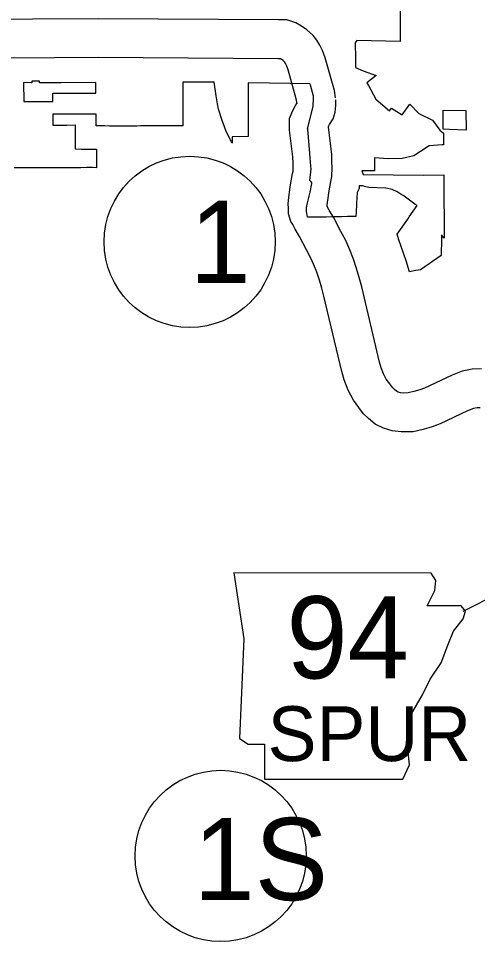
# Model space of a CAD drawing. Extents: x 670147 to 673275, y 705573 to 707613.
# Drawn here: x 670649.9 to 670703, y 707193.3 to 707300.1 of the extents above; entities that cross this region are included whole.
import ezdxf

# ---------------------------------------------------------------- set-up
doc = ezdxf.new("R2010")
doc.units = 0
for name, color, linetype in [('10', 7, 'Continuous'), ('21', 7, 'Continuous'), ('27', 7, 'Continuous'), ('6', 7, 'Continuous')]:
    doc.layers.add(name, color=color, linetype=linetype)

msp = doc.modelspace()

# ---------------------------------------------------------------- linework, layer by layer
at = {"layer": '10'}
for points in [[(670686.58, 707290.93), (670686.45, 707291.76), (670685.39, 707295.54), (670685.09, 707296.38), (670684.78, 707297), (670684.42, 707297.58), (670684.01, 707298.13), (670683.27, 707298.79), (670682.63, 707299.22), (670682, 707299.6), (670680.95, 707299.92), (670679.98, 707299.93), (670659.13, 707300.07), (670643.9, 707299.97), (670623.24, 707299.95), (670622.57, 707299.9), (670622.06, 707299.8), (670621.6, 707299.73), (670620.82, 707299.58), (670620.26, 707299.49), (670616.24, 707299.62)], [(670682.13, 707290.24), (670682.04, 707290.81), (670681.11, 707294.17), (670680.95, 707294.59), (670680.84, 707294.8), (670680.69, 707295.06), (670680.67, 707295.08), (670680.51, 707295.22), (670680.22, 707295.42), (670680.2, 707295.43), (670679.93, 707295.43), (670659.13, 707295.57), (670643.92, 707295.47), (670623.4, 707295.45), (670623.15, 707295.43), (670622.85, 707295.37), (670622.38, 707295.29), (670621.61, 707295.15), (670620.58, 707294.97), (670602.62, 707295.57)], [(670703.3, 707255.07), (670702.94, 707255.06), (670702.53, 707254.98), (670701.84, 707254.71), (670698.67, 707253.21), (670697.75, 707252.85), (670696.71, 707252.57), (670695.54, 707252.3), (670694.16, 707252.27), (670693.12, 707252.4), (670692.14, 707252.7), (670691.17, 707253.19), (670690.4, 707253.82), (670689.83, 707254.38), (670689.28, 707255.11), (670688.64, 707255.96), (670688.03, 707257.1), (670687.56, 707258.29), (670687.3, 707259.27), (670685.24, 707267.97), (670685, 707268.91), (670684.71, 707269.81), (670684.42, 707270.74), (670684.06, 707271.6), (670683.7, 707272.46), (670683.21, 707273.35), (670682.43, 707274.86), (670681.91, 707275.74), (670681.64, 707276.27), (670681.43, 707276.63), (670681.13, 707277.5), (670681.13, 707278.15), (670681.11, 707278.64), (670681.17, 707279.37), (670681.26, 707279.96), (670681.35, 707280.62), (670681.62, 707282.15), (670681.69, 707282.43), (670681.7, 707282.8), (670681.67, 707283.37), (670681.66, 707284.08), (670681.26, 707287.18), (670681.24, 707287.75), (670681.27, 707288.54), (670681.52, 707289.17), (670681.79, 707289.77), (670682.12, 707290.28), (670682.11, 707290.5)], [(670703.47, 707259.58), (670702.39, 707259.55), (670701.24, 707259.3), (670700.08, 707258.86), (670696.88, 707257.34), (670696.34, 707257.13), (670695.62, 707256.94), (670694.96, 707256.79), (670694.39, 707256.77), (670694.08, 707256.81), (670693.83, 707256.89), (670693.63, 707256.99), (670693.41, 707257.17), (670693.22, 707257.36), (670692.87, 707257.82), (670692.45, 707258.38), (670692.12, 707259), (670691.84, 707259.7), (670691.66, 707260.36), (670689.61, 707269.05), (670689.33, 707270.15), (670689, 707271.17), (670688.65, 707272.27), (670688.22, 707273.33), (670687.76, 707274.41), (670687.19, 707275.47), (670686.37, 707277.04), (670685.85, 707277.92), (670685.63, 707278.36), (670685.62, 707278.55), (670685.64, 707278.82), (670685.72, 707279.31), (670685.8, 707279.94), (670686.03, 707281.24), (670686.17, 707281.83), (670686.2, 707282.84), (670686.17, 707283.5), (670686.16, 707284.38), (670685.75, 707287.58), (670685.75, 707287.61), (670685.75, 707287.61), (670685.9, 707287.84), (670686.32, 707288.47), (670686.53, 707289.25), (670686.63, 707290.04), (670686.6, 707290.67)]]:
    msp.add_lwpolyline(points, dxfattribs=at)
at = {"layer": '21'}
msp.add_line((670701.34, 707231.53), (670721.03, 707241.6), dxfattribs=at)
msp.add_lwpolyline([(670674.83, 707235.97), (670675.97, 707228.36), (670675.46, 707216.81), (670676.48, 707216.18), (670678.38, 707216.18), (670678.38, 707212.12), (670694.37, 707212.12), (670695.13, 707213.77), (670694.88, 707216.43), (670695.26, 707219.48), (670696.65, 707221.89), (670697.54, 707223.67), (670698.81, 707225.57), (670699.57, 707227.6), (670700.21, 707229.25), (670701.35, 707230.65), (670701.6, 707231.53), (670701.09, 707232.17), (670697.16, 707232.17), (670698.05, 707233.94), (670698.17, 707235.09), (670697.65, 707235.96)], close=True, dxfattribs=at)
at = {"layer": '27'}
for centre in [(670669.72, 707274.26), (670673.3, 707203.24)]:
    msp.add_circle(centre, 9.9, dxfattribs=at)
at = {"layer": '6'}
for points in [[(670694.08, 707307.34), (670694.06, 707297.42), (670689.06, 707297.54), (670689.03, 707297.54), (670688.85, 707297.28), (670688.87, 707295.5), (670688.87, 707294.6), (670688.87, 707294.41), (670689.78, 707294.03), (670691.27, 707293.48), (670690.2, 707292.65), (670690.41, 707292.33), (670691.24, 707290.77), (670692.82, 707289.42), (670693.04, 707289.73), (670694.27, 707288.96), (670695.18, 707290.19), (670696.23, 707289.11), (670697.81, 707288.32), (670698.62, 707287.19), (670699.05, 707286.83), (670699.06, 707285.86), (670699.06, 707285.49), (670699.03, 707285.49), (670698.89, 707285.47), (670697.41, 707285.37), (670696.39, 707284.7), (670695.64, 707284.21), (670694.3, 707283.91), (670692.68, 707283.87), (670691.1, 707283.96), (670691.1, 707283.58), (670691.1, 707282.46), (670689.63, 707282.49), (670689.77, 707282.03), (670696.72, 707281.99), (670699.09, 707282.02), (670699.11, 707279.03), (670699.13, 707277.17), (670699.13, 707276.92), (670699.15, 707274.69), (670698.82, 707275.08), (670698.82, 707274.78), (670698.82, 707274.59), (670698.81, 707272.7), (670696.39, 707271.02), (670695.86, 707270.93), (670695.15, 707270.81), (670694.75, 707272.05), (670694.44, 707272.96), (670693.91, 707274.51), (670693.69, 707275.13), (670694.92, 707276.9), (670695.11, 707277.17), (670696, 707278.45), (670695.76, 707278.63), (670694.53, 707279.54), (670694.4, 707279.63), (670694.17, 707279.75), (670693.7, 707280.06), (670693.13, 707280.31), (670692.39, 707280.46), (670690.44, 707280.55), (670689.91, 707280.67), (670689.73, 707280.72), (670689.32, 707280.72), (670689.32, 707280.44), (670689.09, 707279.95), (670689.02, 707278.72), (670688.96, 707277.56), (670688.94, 707277.27), (670688.94, 707277.19), (670688.81, 707277.19), (670687.98, 707277.18), (670687.26, 707277.17), (670687.15, 707277.16), (670686.91, 707277.16), (670686.33, 707277.15), (670685.5, 707277.13), (670683.53, 707277.11), (670683.34, 707277.11), (670683.29, 707277.35), (670683.25, 707277.56), (670683.23, 707277.77), (670683.23, 707277.98), (670683.24, 707278.19), (670683.24, 707278.22), (670683.24, 707278.26), (670683.26, 707278.4), (670683.29, 707278.61), (670683.64, 707279.99), (670683.85, 707281.02), (670683.81, 707281.14), (670683.83, 707281.14), (670683.62, 707281.34), (670683.75, 707282.71), (670683.74, 707283), (670683.6, 707284.48)], [(670683.6, 707284.48), (670683.36, 707287.31), (670683.4, 707287.34), (670683.35, 707287.34), (670683.75, 707288.97), (670683.98, 707289.97), (670684.02, 707290.84), (670684.03, 707291.1), (670683.68, 707292.39), (670683.65, 707292.52), (670678.96, 707292.61), (670676.48, 707292.65), (670676.48, 707291.34), (670676.49, 707288.45), (670676.49, 707287.55), (670676.49, 707286.45), (670674.64, 707286.4), (670674.63, 707285.67), (670673.94, 707287.02), (670673.76, 707287.58), (670673.49, 707288.3), (670673.06, 707289.62), (670672.92, 707290.22), (670672.78, 707291.16), (670672.55, 707292.73), (670668.91, 707292.72), (670668.91, 707292.09), (670668.92, 707291.42), (670668.93, 707290.76), (670668.93, 707290.23), (670668.93, 707289.71), (670668.94, 707289.18), (670668.94, 707288.55), (670668.94, 707287.69), (670668.47, 707287.69), (670667.29, 707287.68), (670667.03, 707287.68), (670666.76, 707287.67), (670666.24, 707287.67), (670665.71, 707287.67), (670665.32, 707287.66), (670665.18, 707287.67), (670664.66, 707287.67), (670664.13, 707287.66), (670664.02, 707287.66), (670663.6, 707287.65), (670663.08, 707287.65), (670662.55, 707287.65), (670662.45, 707287.65), (670662.38, 707287.65), (670662.02, 707287.65), (670661.5, 707287.65), (670660.97, 707287.65), (670660.45, 707287.65), (670659.92, 707287.66), (670659.08, 707287.66), (670658.91, 707287.66), (670658.91, 707287.78), (670658.9, 707289.01), (670653.9, 707289.01), (670653.9, 707287.77), (670654.26, 707287.77), (670654.9, 707287.77), (670655.53, 707287.77), (670656.49, 707287.78), (670656.47, 707286.56), (670656.47, 707285.78), (670656.47, 707285), (670657.19, 707284.97), (670657.9, 707284.98), (670658.73, 707284.99), (670658.93, 707284.99), (670658.94, 707284.11), (670658.95, 707283.01), (670658.95, 707282.83), (670658.48, 707282.84), (670657.84, 707282.84), (670657.15, 707282.83), (670656.45, 707282.83), (670655.79, 707282.83), (670655.15, 707282.83), (670654.52, 707282.83), (670653.99, 707282.83), (670653.88, 707282.83), (670653.25, 707282.83), (670652.61, 707282.83), (670651.98, 707282.82), (670651.52, 707282.82), (670651.35, 707282.82), (670650.71, 707282.82), (670650.08, 707282.82), (670649.44, 707282.82)]]:
    msp.add_lwpolyline(points, dxfattribs=at)
for points in [[(670653.91, 707290.51), (670653.91, 707291.47), (670658.88, 707291.47), (670658.87, 707292.7), (670654.83, 707292.64), (670654.42, 707292.65), (670653.92, 707292.65), (670653.61, 707292.65), (670652.36, 707292.66), (670652.36, 707292.85), (670651.48, 707292.85), (670651.48, 707292.66), (670651.44, 707292.66), (670650.52, 707292.67), (670650.54, 707290.51), (670651.36, 707290.51), (670651.73, 707290.51), (670652.11, 707290.51), (670652.48, 707290.51), (670653.56, 707290.51)], [(670701.67, 707287.19), (670699.71, 707287.26), (670699.04, 707287.28), (670699.02, 707289.47), (670701.66, 707289.44)]]:
    msp.add_lwpolyline(points, close=True, dxfattribs=at)

# ---------------------------------------------------------------- texts
at = {"layer": '21'}
for s, height, p in [('94', 9.504, (670680.91, 707223.77)), ('SPUR', 6.336, (670678.73, 707214.21))]:
    msp.add_text(s, height=height, dxfattribs=at).set_placement(p)
at = {"layer": '27'}
for s, height, p in [('1', 9.5, (670669.72, 707269.51)), ('1S', 9.504, (670670.17, 707198.13))]:
    msp.add_text(s, height=height, dxfattribs=at).set_placement(p)

doc.saveas('drawing.dxf')
